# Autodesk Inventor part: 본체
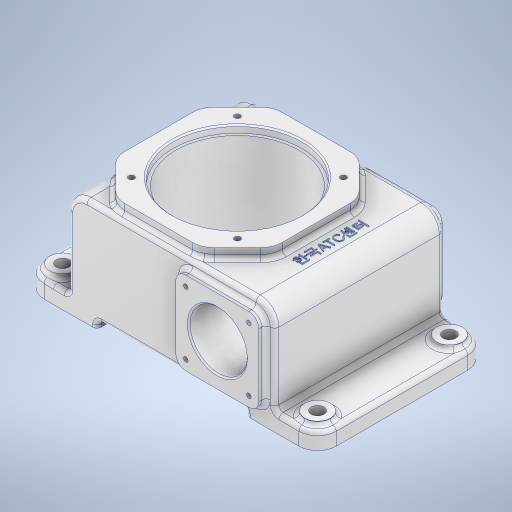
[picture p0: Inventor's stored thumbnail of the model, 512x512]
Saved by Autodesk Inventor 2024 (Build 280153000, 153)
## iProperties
Created: 2026-02
Part Number: 본체
Material: 알루미늄 6061
Document SubType Name: Modeling
Designer: 2-10
Density: 2.7 g/cm^3
Appearance: 알루미늄 - 평지
Author: 2-10
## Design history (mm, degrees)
sketch "스케치1"
  geometry: L1 (-72, 37.5)-(72, 37.5); L2 (72, 37.5)-(72, -37.5); L3 (72, -37.5)-(-72, -37.5); L4 (-72, -37.5)-(-72, 37.5); L5 (-72, 37.5)-(72, -37.5); L6 (72, 37.5)-(-72, -37.5); 1 further point
  constraints: 12 end point, 2 midpoint, 2 parallel, 1 horizontal, 1 perpendicular
  dimensions: "d0" = 144 distance of L1.start L1.end; "d1" = 75 distance of L1.end L2.end
extrude "돌출1" new body sketch "스케치1" stored distance "d2" = 118; taper "d3" = 0 deg
sketch "스케치2"
  geometry: L1 (-30, -118)-(20, -118); L2 (20, -118)-(20, 0); L3 (20, 0)-(-30, 0); L4 (-30, 0)-(-30, -118); L5 (124, -118)-(174, -118); L6 (174, -118)-(174, 0); L7 (174, 0)-(124, 0); L8 (124, 0)-(124, -118); L9 (144, -118)-(0, -118) reference; L10 (0, 0)-(144, 0) reference; L11 (72, -118)-(72, 0); L12 (144, 0)-(0, 0) reference; L13 (144, -118)-(144, 0) reference; 1 further point
  constraints: 18 end point, 4 horizontal alignment, 4 parallel, 3 perpendicular, 2 horizontal, 2 midpoint, 2 point on line, 1 other
  dimensions: "d4" = 50 distance of L2.end L3.end; "d5" = 50 distance of L6.end L7.end; "d17" = 30 distance between parallel lines of L6 L13
extrude "돌출2" join sketch "스케치2" distance "d7" = 12; taper "d8" = 0 deg
extrude "돌출3" cut sketch "스케치2" distance "d9" = 5; taper "d10" = 0 deg
fillet "모깎기1" dims "d11" = 13
sketch "스케치3"
  geometry: L1 (66, 31.5)-(66, -26.5); L2 (66, -26.5)-(8, -26.5); L3 (8, -26.5)-(8, 31.5); L4 (8, 31.5)-(66, 31.5); L5 (52, -37.5)-(89, -37.5) reference; L6 (102, -25.5)-(102, -37.5) reference; 2 further points
  constraints: 8 end point, 1 horizontal, 9 other
  dimensions: "d12" = 58 distance of L1.start L1.end; "d13" = 40 distance from line of point (37, 2.5) L5; "d16" = 65 horizontal distance of L6.end point (37, 2.5)
extrude "돌출4" join sketch "스케치3" stored distance "d18" = 128; taper "d19" = 0 deg
sketch "스케치4"
  geometry: L1 (114, 89)-(114, 29); L2 (89, 4)-(29, 4); L3 (4, 29)-(4, 89); L4 (29, 114)-(89, 114); L5 (4, 89)-(29, 114); L6 (4, 29)-(29, 4); L7 (89, 4)-(114, 29); L8 (114, 89)-(89, 114); L9 (174, 13)-(174, 105) reference; 8 further points
  constraints: 16 end point, 8 point on line, 1 coincident, 1 horizontal alignment, 1 midpoint, 1 vertical, 9 other
  dimensions: "d20" = 110 distance of point (114, 114) point (114, 4); "d21" = 25 distance of L3.end point (4, 114); "d22" = 25 distance of L4.start point (4, 114) (= d21); "d23" = 25 distance of L3.start point (4, 4) (= d21); "d24" = 25 distance of L2.end point (4, 4) (= d23); "d25" = 25 distance of L2.start point (114, 4) (= d21); "d26" = 25 distance of L1.end point (114, 4) (= d25); "d27" = 25 distance of L1.start point (114, 114) (= d21); "d28" = 25 distance of L4.end point (114, 114) (= d27); "d110" = 115 distance from line of point (59, 59) L9
extrude "돌출5" join sketch "스케치4" distance "d29" = 7; taper "d30" = 0 deg
sketch "스케치5"
  geometry: L1 (29, 114)-(4, 89) reference; L2 (4, 89)-(4, 29) reference; L3 (114, 89)-(89, 114) reference; L4 (4, 29)-(114, 89); L5 (29, 4)-(4, 29) reference; L6 (4, 29)-(4, 89) reference; L7 (4, 89)-(29, 114) reference; L8 (29, 114)-(89, 114) reference; L9 (89, 114)-(114, 89) reference; L10 (114, 89)-(114, 29) reference; L11 (114, 29)-(89, 4) reference; L12 (89, 4)-(29, 4) reference; L13 (4, 89)-(114, 29); 3 further points
  constraints: 4 end point, 2 coincident, 1 midpoint
  node "절단 모서리 투영3"
hole "구멍1" sketch "스케치5" diameter "d31" = 86; stored, may be unused: countersink angle "d35" = 90 deg, drill point angle "d37" = 0 deg; dims "d32" = 8, "d33" = 4, "d34" = 2, "d36" = 66
sketch "스케치6"
  geometry: 5 further points
  constraints: 1 coincident, 1 other
hole "구멍2" sketch "스케치6" at (59, 59) diameter "d38" = 90; stored, may be unused: countersink angle "d42" = 90 deg, drill point angle "d44" = 0 deg; dims "d39" = 6, "d40" = 4, "d41" = 2, "d43" = 5
node "작업 평면1"
sketch "스케치8"
  geometry: C1 r 25 at (0, 0); C2 r 45 at (0, 0) reference; C3 r 43 at (0, 0) reference; 1 further point
  constraints: 2 coincident, 1 centre point
  dimensions: "d47" = 50 diameter of C1
extrude "돌출6" join sketch "스케치8" distance "d48" = 7; taper "d49" = 45 deg
sketch "스케치10"
  geometry: C1 r 43 at (0, 0) reference; 2 further points
  constraints: 2 coincident
hole "구멍3" sketch "스케치10" at (0, 0) diameter "d50" = 40; stored, may be unused: countersink angle "d54" = 90 deg, drill point angle "d56" = 0 deg; dims "d51" = 6, "d52" = 4, "d53" = 2, "d55" = 11
fillet "모깎기2" dims "d57" = 1.5
chamfer "모따기1" distance "d58" = 1; stored, may be unused: second distance "d59" = 2, angle "d60" = 45 deg
fillet "모깎기3" dims "d61" = 3
sketch "스케치11"
  geometry: L1 (8, 31.5)-(8, -26.5) reference; L2 (8, -26.5)-(66, -26.5) reference; 2 further points
  dimensions: "d62" = 29 distance from line of L1 point (37, 2.5); "d63" = 29 distance from line of L2 point (37, 2.5)
hole "구멍4" sketch "스케치11" at (37, 2.5) diameter "d64" = 40; stored, may be unused: countersink angle "d68" = 90 deg, drill point angle "d70" = 0 deg; dims "d65" = 6, "d66" = 4, "d67" = 2, "d69" = 11
sketch "스케치12"
  geometry: L1 (96, 96)-(96, 22); L2 (96, 22)-(22, 22); L3 (22, 22)-(22, 96); L4 (22, 96)-(96, 96); C1 r 46 at (59, 59) reference; 2 further points
  constraints: 8 end point, 1 coincident, 1 horizontal, 9 other
  dimensions: "d71" = 74 distance of L1.start L1.end
hole "구멍5" sketch "스케치12" at (22, 96), (96, 96), (96, 22), (22, 22) diameter "d72" = 4.134; stored, may be unused: countersink angle "d76" = 90 deg, drill point angle "d78" = 118 deg; dims "d73" = 10, "d74" = 4, "d75" = 2, "d77" = 12
sketch "스케치13"
  geometry: L1 (59, 24.5)-(59, -19.5); L2 (59, -19.5)-(15, -19.5); L3 (15, -19.5)-(15, 24.5); L4 (15, 24.5)-(59, 24.5); C1 r 20 at (37, 2.5) reference; 2 further points
  constraints: 8 end point, 1 coincident, 1 horizontal, 9 other
  dimensions: "d79" = 44 distance of L1.start L1.end
hole "구멍6" sketch "스케치13" at (15, 24.5), (59, 24.5), (59, -19.5), (15, -19.5) diameter "d80" = 3.242; stored, may be unused: countersink angle "d84" = 90 deg, drill point angle "d86" = 118 deg; dims "d81" = 8, "d82" = 4, "d83" = 2, "d85" = 10
sketch "스케치14"
  geometry: L1 (161, 0)-(144, 0) reference; L2 (144, 0)-(138, 0) reference; L3 (138, 0)-(138, -5) reference; L4 (138, -5)-(80, -5) reference; L5 (80, -5)-(80, 0) reference; L6 (80, 0)-(0, 0) reference; L7 (0, 118)-(0, 0) reference; L8 (0, 118)-(80, 118) reference; L9 (80, 118)-(80, 123) reference; L10 (80, 123)-(138, 123) reference; L11 (138, 123)-(138, 118) reference; L12 (138, 118)-(144, 118) reference; L13 (144, 0)-(144, 118) reference; L14 (174, 105)-(174, 13) reference; L15 (144, 118)-(161, 118) reference; L16 (0, 0)-(-17, 0) reference; L17 (-30, 13)-(-30, 105) reference; L18 (-17, 118)-(0, 118) reference; C1 r 19.914 at (59, 59) reference; C2 r 9 at (-17, 105); C3 r 9 at (161, 105); C4 r 9 at (-17, 13); C5 r 9 at (161, 13); A1 r 13 centre (161, 13) between (161, 0) and (174, 13) reference; A2 r 13 centre (161, 105) between (174, 105) and (161, 118) reference; A3 r 13 centre (-17, 13) between (-30, 13) and (-17, 0) reference; A4 r 13 centre (-17, 105) between (-17, 118) and (-30, 105) reference; 1 further point
  constraints: 4 centre point, 4 coincident, 3 equal radius
  dimensions: "d87" = 18 diameter of C2
extrude "돌출7" join sketch "스케치14" distance "d88" = 3; taper "d89" = 0 deg
sketch "스케치15"
  geometry: C1 r 9 at (0, 0) reference; C2 r 9 at (0, 92) reference; C3 r 9 at (178, 0) reference; C4 r 9 at (178, 92) reference; 5 further points
  constraints: 4 coincident
hole "구멍7" sketch "스케치15" at (0, 0), (0, 92), (178, 0), (178, 92) diameter "d90" = 9; stored, may be unused: countersink angle "d94" = 90 deg, drill point angle "d96" = 118 deg; dims "d91" = 8, "d92" = 4, "d93" = 2, "d95" = 10
fillet "모깎기4" dims "d97" = 15
fillet "모깎기12" dims "d105" = 7
fillet "모깎기13" dims "d106" = 3
fillet "모깎기5" dims "d98" = 13
fillet "모깎기6" dims "d99" = 3
fillet "모깎기8" dims "d101" = 3
fillet "모깎기9" dims "d102" = 3
fillet "모깎기10" dims "d103" = 3
chamfer "모따기2" distance "d107" = 1; stored, may be unused: second distance "d108" = 2, angle "d109" = 45 deg
sketch "스케치16"
  geometry: C1 r 46 at (-32.033, 56) reference; 2 further points
  constraints: 1 horizontal alignment, 1 other
  dimensions: "d111" = 65 distance of point (32.967, 56) C1.centre
feature "엠보싱1" sketch "스케치16" dims "d4" = 50, "d5" = 50, "d17" = 30, "d112" = 0.5, "d113" = 0
fillet "모깎기14" dims "d114" = 3
node "솔리드1"
mirror "미러1"
mirror "미러3"
node "투영된 루프1"
node "절단 모서리 투영2"
feature "A9D066F2-1C7D-4E18-AEED-F7BC21143FA4" dims "d31" = 86, "d32" = 8, "d33" = 4, "d34" = 2, "d35" = 90 deg, "d36" = 66, "d37" = 0
other parameters: "d45" = 6
